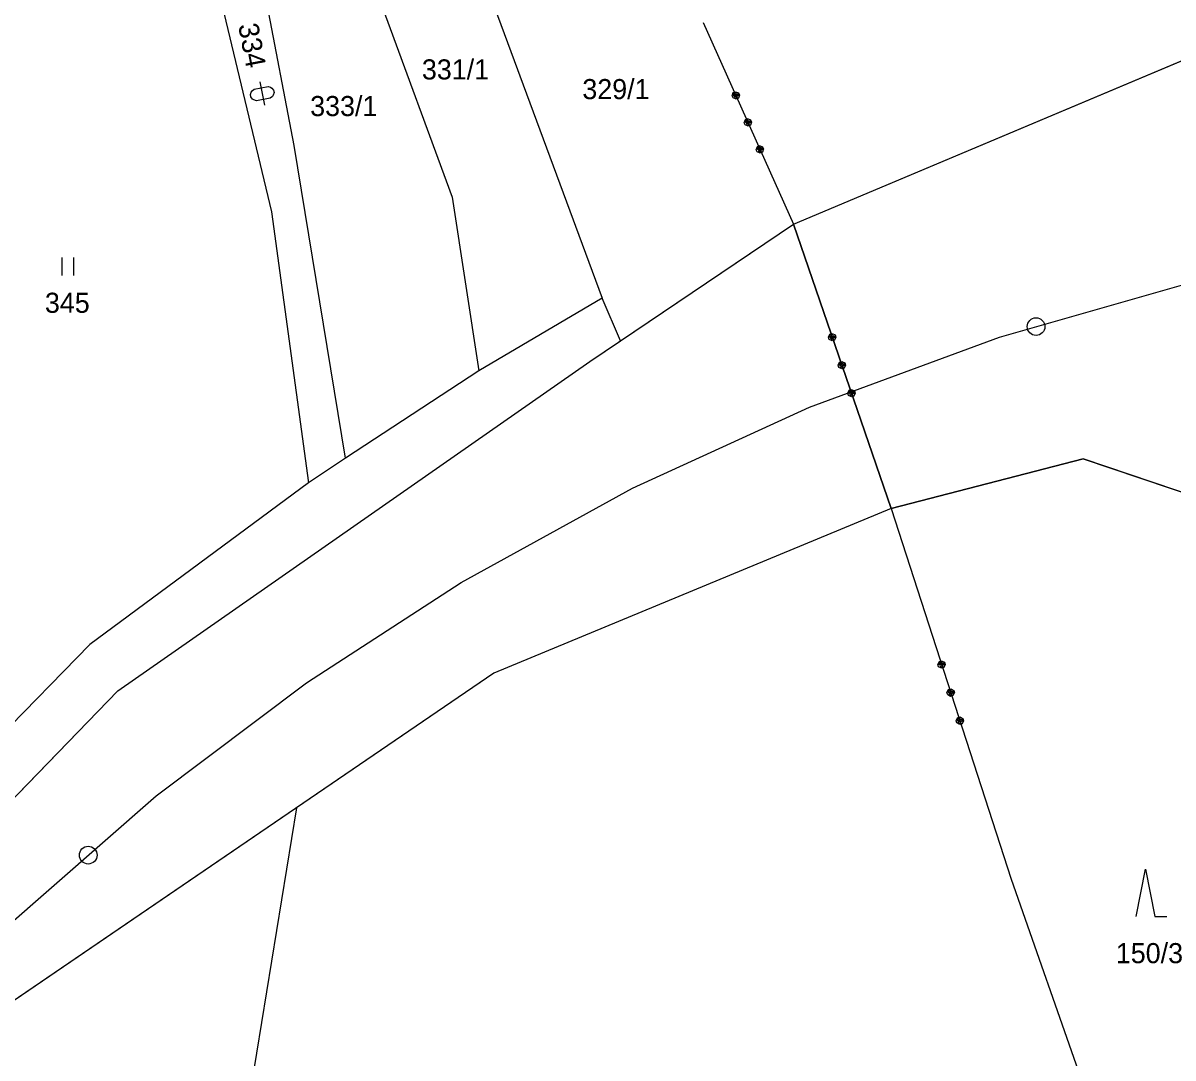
# Model space of a CAD drawing. Extents: x -866656 to -858817, y -1041816 to -1038653.
# Drawn here: x -863689.5 to -863592.2, y -1039792.1 to -1039704.6 of the extents above; entities that cross this region are included whole.
import ezdxf

# ---------------------------------------------------------------- set-up
doc = ezdxf.new("R2010")
doc.units = 0
for name, color, linetype in [('SZDC', 7, 'Continuous'), ('Vrstva 1', 7, 'Continuous'), ('Vrstva 3', 7, 'Continuous'), ('Vrstva 53', 7, 'Continuous'), ('Vrstva 7', 7, 'Continuous')]:
    doc.layers.add(name, color=color, linetype=linetype)

msp = doc.modelspace()

# ---------------------------------------------------------------- linework, layer by layer
at = {"layer": 'SZDC'}
for points in [[(-863578.248, -1039748.71), (-863599.78, -1039741.44), (-863616.033, -1039745.621), (-863624.298, -1039721.586), (-863586.128, -1039705.518)], [(-863782.379, -1039903.176), (-863748.01, -1039848.49), (-863725.76, -1039812), (-863710.18, -1039790.69), (-863681.49, -1039761.05), (-863641.52, -1039733.19), (-863638.923, -1039731.44), (-863624.298, -1039721.586), (-863616.033, -1039745.621), (-863649.65, -1039759.58), (-863666.36, -1039770.968), (-863692.07, -1039788.49), (-863713.604, -1039813.597), (-863754.65, -1039882.17)]]:
    msp.add_lwpolyline(points, dxfattribs=at)
at = {"layer": 'Vrstva 1'}
for p, q in [((-863666.548, -1039714.91), (-863673.173, -1039680.298)), ((-863677.665, -1039682.095), (-863668.457, -1039720.524)), ((-863653.972, -1039691.414), (-863640.48, -1039727.826)), ((-863659.137, -1039703.092), (-863653.186, -1039719.289)), ((-863624.298, -1039721.586), (-863586.128, -1039705.518)), ((-863670.117, -1039710.28), (-863669.939, -1039710.145)), ((-863669.939, -1039710.145), (-863668.76, -1039709.919)), ((-863669.444, -1039709.541), (-863669.068, -1039711.505)), ((-863668.76, -1039709.919), (-863668.545, -1039709.98)), ((-863668.545, -1039709.98), (-863668.428, -1039710.059)), ((-863668.428, -1039710.059), (-863668.292, -1039710.237)), ((-863670.257, -1039710.613), (-863670.196, -1039710.397)), ((-863670.219, -1039710.809), (-863670.257, -1039710.613)), ((-863670.083, -1039710.987), (-863670.219, -1039710.809)), ((-863670.196, -1039710.397), (-863670.117, -1039710.28)), ((-863669.966, -1039711.066), (-863670.083, -1039710.987)), ((-863669.751, -1039711.127), (-863669.966, -1039711.066)), ((-863668.572, -1039710.901), (-863669.751, -1039711.127)), ((-863668.395, -1039710.765), (-863668.572, -1039710.901)), ((-863668.315, -1039710.648), (-863668.395, -1039710.765)), ((-863668.255, -1039710.433), (-863668.315, -1039710.648)), ((-863668.292, -1039710.237), (-863668.255, -1039710.433)), ((-863662.208, -1039741.384), (-863666.548, -1039714.91)), ((-863653.186, -1039719.289), (-863650.91, -1039733.997)), ((-863668.457, -1039720.524), (-863665.337, -1039743.47)), ((-863641.52, -1039733.19), (-863624.298, -1039721.586)), ((-863686.229, -1039724.407), (-863686.229, -1039725.907)), ((-863685.229, -1039724.407), (-863685.229, -1039725.907)), ((-863640.48, -1039727.826), (-863650.91, -1039733.997)), ((-863638.923, -1039731.44), (-863640.48, -1039727.826)), ((-863681.49, -1039761.05), (-863641.52, -1039733.19)), ((-863650.91, -1039733.997), (-863662.208, -1039741.384)), ((-863662.208, -1039741.384), (-863665.337, -1039743.47)), ((-863616.033, -1039745.621), (-863599.78, -1039741.44)), ((-863599.78, -1039741.44), (-863573.262, -1039750.394)), ((-863665.337, -1039743.47), (-863683.849, -1039757.137)), ((-863616.033, -1039745.621), (-863649.65, -1039759.58)), ((-863683.849, -1039757.137), (-863714.528, -1039788.533)), ((-863649.65, -1039759.58), (-863692.07, -1039788.49)), ((-863710.18, -1039790.69), (-863681.49, -1039761.05)), ((-863666.36, -1039770.968), (-863672.36, -1039807.853)), ((-863595.29, -1039780.15), (-863594.49, -1039776.15)), ((-863594.49, -1039776.15), (-863593.69, -1039780.15)), ((-863593.69, -1039780.15), (-863592.69, -1039780.15))]:
    msp.add_line(p, q, dxfattribs=at)
msp.add_lwpolyline([(-863714.673, -1039807.18), (-863703.723, -1039794.072), (-863691.42, -1039781.486), (-863678.245, -1039769.939), (-863665.513, -1039760.373), (-863652.414, -1039751.898), (-863637.916, -1039743.904), (-863622.923, -1039737.063), (-863606.856, -1039731.127), (-863590.069, -1039726.347)], dxfattribs=at)
at = {"layer": 'Vrstva 3'}
for p, q in [((-863631.92, -1039704.52), (-863624.298, -1039721.586)), ((-863631.92, -1039704.52), (-863624.298, -1039721.586)), ((-863629.484, -1039710.71), (-863629.383, -1039710.446)), ((-863629.484, -1039710.71), (-863629.383, -1039710.446)), ((-863629.402, -1039710.892), (-863629.484, -1039710.71)), ((-863629.402, -1039710.892), (-863629.484, -1039710.71)), ((-863629.138, -1039710.993), (-863629.402, -1039710.892)), ((-863629.138, -1039710.993), (-863629.402, -1039710.892)), ((-863629.393, -1039710.669), (-863629.027, -1039710.506)), ((-863629.393, -1039710.669), (-863629.027, -1039710.506)), ((-863629.342, -1039710.537), (-863629.393, -1039710.669)), ((-863629.342, -1039710.537), (-863629.393, -1039710.669)), ((-863629.383, -1039710.446), (-863629.2, -1039710.364)), ((-863629.383, -1039710.446), (-863629.2, -1039710.364)), ((-863628.987, -1039710.597), (-863629.352, -1039710.76)), ((-863628.987, -1039710.597), (-863629.352, -1039710.76)), ((-863629.159, -1039710.455), (-863629.342, -1039710.537)), ((-863629.159, -1039710.455), (-863629.342, -1039710.537)), ((-863628.946, -1039710.688), (-863629.311, -1039710.852)), ((-863628.946, -1039710.688), (-863629.311, -1039710.852)), ((-863629.311, -1039710.852), (-863629.179, -1039710.902)), ((-863629.311, -1039710.852), (-863629.179, -1039710.902)), ((-863629.2, -1039710.364), (-863628.936, -1039710.465)), ((-863629.2, -1039710.364), (-863628.936, -1039710.465)), ((-863629.179, -1039710.902), (-863628.996, -1039710.821)), ((-863629.179, -1039710.902), (-863628.996, -1039710.821)), ((-863628.955, -1039710.912), (-863629.138, -1039710.993)), ((-863628.955, -1039710.912), (-863629.138, -1039710.993)), ((-863629.027, -1039710.506), (-863628.946, -1039710.688)), ((-863629.027, -1039710.506), (-863628.946, -1039710.688)), ((-863628.854, -1039710.648), (-863628.955, -1039710.912)), ((-863628.854, -1039710.648), (-863628.955, -1039710.912)), ((-863628.936, -1039710.465), (-863628.854, -1039710.648)), ((-863628.936, -1039710.465), (-863628.854, -1039710.648)), ((-863628.464, -1039712.992), (-863628.363, -1039712.728)), ((-863628.464, -1039712.992), (-863628.363, -1039712.728)), ((-863628.383, -1039713.175), (-863628.464, -1039712.992)), ((-863628.383, -1039713.175), (-863628.464, -1039712.992)), ((-863628.373, -1039712.952), (-863628.008, -1039712.789)), ((-863628.373, -1039712.952), (-863628.008, -1039712.789)), ((-863628.323, -1039712.82), (-863628.373, -1039712.952)), ((-863628.323, -1039712.82), (-863628.373, -1039712.952)), ((-863628.363, -1039712.728), (-863628.181, -1039712.647)), ((-863628.363, -1039712.728), (-863628.181, -1039712.647)), ((-863627.967, -1039712.88), (-863628.332, -1039713.043)), ((-863627.967, -1039712.88), (-863628.332, -1039713.043)), ((-863628.14, -1039712.738), (-863628.323, -1039712.82)), ((-863628.14, -1039712.738), (-863628.323, -1039712.82)), ((-863627.926, -1039712.971), (-863628.292, -1039713.134)), ((-863627.926, -1039712.971), (-863628.292, -1039713.134)), ((-863628.181, -1039712.647), (-863627.917, -1039712.748)), ((-863628.181, -1039712.647), (-863627.917, -1039712.748)), ((-863628.008, -1039712.789), (-863627.926, -1039712.971)), ((-863628.008, -1039712.789), (-863627.926, -1039712.971)), ((-863627.835, -1039712.93), (-863627.936, -1039713.195)), ((-863627.835, -1039712.93), (-863627.936, -1039713.195)), ((-863627.917, -1039712.748), (-863627.835, -1039712.93)), ((-863627.917, -1039712.748), (-863627.835, -1039712.93)), ((-863628.119, -1039713.276), (-863628.383, -1039713.175)), ((-863628.119, -1039713.276), (-863628.383, -1039713.175)), ((-863628.292, -1039713.134), (-863628.16, -1039713.185)), ((-863628.292, -1039713.134), (-863628.16, -1039713.185)), ((-863628.16, -1039713.185), (-863627.977, -1039713.103)), ((-863628.16, -1039713.185), (-863627.977, -1039713.103)), ((-863627.936, -1039713.195), (-863628.119, -1039713.276)), ((-863627.936, -1039713.195), (-863628.119, -1039713.276)), ((-863627.445, -1039715.275), (-863627.344, -1039715.011)), ((-863627.445, -1039715.275), (-863627.344, -1039715.011)), ((-863627.344, -1039715.011), (-863627.161, -1039714.929)), ((-863627.344, -1039715.011), (-863627.161, -1039714.929)), ((-863627.121, -1039715.021), (-863627.303, -1039715.102)), ((-863627.121, -1039715.021), (-863627.303, -1039715.102)), ((-863627.161, -1039714.929), (-863626.897, -1039715.031)), ((-863627.161, -1039714.929), (-863626.897, -1039715.031)), ((-863627.364, -1039715.458), (-863627.445, -1039715.275)), ((-863627.364, -1039715.458), (-863627.445, -1039715.275)), ((-863627.099, -1039715.559), (-863627.364, -1039715.458)), ((-863627.099, -1039715.559), (-863627.364, -1039715.458)), ((-863627.354, -1039715.234), (-863626.989, -1039715.071)), ((-863627.354, -1039715.234), (-863626.989, -1039715.071)), ((-863627.303, -1039715.102), (-863627.354, -1039715.234)), ((-863627.303, -1039715.102), (-863627.354, -1039715.234)), ((-863626.948, -1039715.163), (-863627.313, -1039715.326)), ((-863626.948, -1039715.163), (-863627.313, -1039715.326)), ((-863626.907, -1039715.254), (-863627.272, -1039715.417)), ((-863626.907, -1039715.254), (-863627.272, -1039715.417)), ((-863627.272, -1039715.417), (-863627.14, -1039715.468)), ((-863627.272, -1039715.417), (-863627.14, -1039715.468)), ((-863627.14, -1039715.468), (-863626.958, -1039715.386)), ((-863627.14, -1039715.468), (-863626.958, -1039715.386)), ((-863626.917, -1039715.477), (-863627.099, -1039715.559)), ((-863626.917, -1039715.477), (-863627.099, -1039715.559)), ((-863626.989, -1039715.071), (-863626.907, -1039715.254)), ((-863626.989, -1039715.071), (-863626.907, -1039715.254)), ((-863626.816, -1039715.213), (-863626.917, -1039715.477)), ((-863626.816, -1039715.213), (-863626.917, -1039715.477)), ((-863626.897, -1039715.031), (-863626.816, -1039715.213)), ((-863626.897, -1039715.031), (-863626.816, -1039715.213)), ((-863624.298, -1039721.586), (-863616.033, -1039745.621)), ((-863624.298, -1039721.586), (-863616.033, -1039745.621)), ((-863621.327, -1039731.148), (-863621.203, -1039730.894)), ((-863621.327, -1039731.148), (-863621.203, -1039730.894)), ((-863621.262, -1039731.337), (-863621.327, -1039731.148)), ((-863621.262, -1039731.337), (-863621.327, -1039731.148)), ((-863621.008, -1039731.461), (-863621.262, -1039731.337)), ((-863621.008, -1039731.461), (-863621.262, -1039731.337)), ((-863621.233, -1039731.115), (-863620.855, -1039730.985)), ((-863621.233, -1039731.115), (-863620.855, -1039730.985)), ((-863621.171, -1039730.988), (-863621.233, -1039731.115)), ((-863621.171, -1039730.988), (-863621.233, -1039731.115)), ((-863621.203, -1039730.894), (-863621.014, -1039730.829)), ((-863621.203, -1039730.894), (-863621.014, -1039730.829)), ((-863620.822, -1039731.08), (-863621.2, -1039731.21)), ((-863620.822, -1039731.08), (-863621.2, -1039731.21)), ((-863620.982, -1039730.923), (-863621.171, -1039730.988)), ((-863620.982, -1039730.923), (-863621.171, -1039730.988)), ((-863620.79, -1039731.174), (-863621.168, -1039731.304)), ((-863620.79, -1039731.174), (-863621.168, -1039731.304)), ((-863621.168, -1039731.304), (-863621.041, -1039731.367)), ((-863621.168, -1039731.304), (-863621.041, -1039731.367)), ((-863621.041, -1039731.367), (-863620.852, -1039731.301)), ((-863621.041, -1039731.367), (-863620.852, -1039731.301)), ((-863621.014, -1039730.829), (-863620.76, -1039730.953)), ((-863621.014, -1039730.829), (-863620.76, -1039730.953)), ((-863620.819, -1039731.396), (-863621.008, -1039731.461)), ((-863620.819, -1039731.396), (-863621.008, -1039731.461)), ((-863620.855, -1039730.985), (-863620.79, -1039731.174)), ((-863620.855, -1039730.985), (-863620.79, -1039731.174)), ((-863620.695, -1039731.142), (-863620.819, -1039731.396)), ((-863620.695, -1039731.142), (-863620.819, -1039731.396)), ((-863620.76, -1039730.953), (-863620.695, -1039731.142)), ((-863620.76, -1039730.953), (-863620.695, -1039731.142)), ((-863620.514, -1039733.512), (-863620.39, -1039733.258)), ((-863620.514, -1039733.512), (-863620.39, -1039733.258)), ((-863620.449, -1039733.701), (-863620.514, -1039733.512)), ((-863620.449, -1039733.701), (-863620.514, -1039733.512)), ((-863620.42, -1039733.479), (-863620.042, -1039733.349)), ((-863620.42, -1039733.479), (-863620.042, -1039733.349)), ((-863620.358, -1039733.352), (-863620.42, -1039733.479)), ((-863620.358, -1039733.352), (-863620.42, -1039733.479)), ((-863620.39, -1039733.258), (-863620.201, -1039733.193)), ((-863620.39, -1039733.258), (-863620.201, -1039733.193)), ((-863620.009, -1039733.444), (-863620.387, -1039733.574)), ((-863620.009, -1039733.444), (-863620.387, -1039733.574)), ((-863620.169, -1039733.287), (-863620.358, -1039733.352)), ((-863620.169, -1039733.287), (-863620.358, -1039733.352)), ((-863620.201, -1039733.193), (-863619.947, -1039733.317)), ((-863620.201, -1039733.193), (-863619.947, -1039733.317)), ((-863620.042, -1039733.349), (-863619.977, -1039733.538)), ((-863620.042, -1039733.349), (-863619.977, -1039733.538)), ((-863619.882, -1039733.506), (-863620.006, -1039733.76)), ((-863619.882, -1039733.506), (-863620.006, -1039733.76)), ((-863619.947, -1039733.317), (-863619.882, -1039733.506)), ((-863619.947, -1039733.317), (-863619.882, -1039733.506)), ((-863620.195, -1039733.825), (-863620.449, -1039733.701)), ((-863620.195, -1039733.825), (-863620.449, -1039733.701)), ((-863619.977, -1039733.538), (-863620.355, -1039733.669)), ((-863619.977, -1039733.538), (-863620.355, -1039733.669)), ((-863620.355, -1039733.669), (-863620.228, -1039733.731)), ((-863620.355, -1039733.669), (-863620.228, -1039733.731)), ((-863620.228, -1039733.731), (-863620.039, -1039733.666)), ((-863620.228, -1039733.731), (-863620.039, -1039733.666)), ((-863620.006, -1039733.76), (-863620.195, -1039733.825)), ((-863620.006, -1039733.76), (-863620.195, -1039733.825)), ((-863619.701, -1039735.876), (-863619.577, -1039735.622)), ((-863619.701, -1039735.876), (-863619.577, -1039735.622)), ((-863619.636, -1039736.065), (-863619.701, -1039735.876)), ((-863619.636, -1039736.065), (-863619.701, -1039735.876)), ((-863619.382, -1039736.189), (-863619.636, -1039736.065)), ((-863619.382, -1039736.189), (-863619.636, -1039736.065)), ((-863619.607, -1039735.844), (-863619.229, -1039735.713)), ((-863619.607, -1039735.844), (-863619.229, -1039735.713)), ((-863619.545, -1039735.716), (-863619.607, -1039735.844)), ((-863619.545, -1039735.716), (-863619.607, -1039735.844)), ((-863619.577, -1039735.622), (-863619.388, -1039735.557)), ((-863619.577, -1039735.622), (-863619.388, -1039735.557)), ((-863619.196, -1039735.808), (-863619.574, -1039735.938)), ((-863619.196, -1039735.808), (-863619.574, -1039735.938)), ((-863619.356, -1039735.651), (-863619.545, -1039735.716)), ((-863619.356, -1039735.651), (-863619.545, -1039735.716)), ((-863619.164, -1039735.903), (-863619.542, -1039736.033)), ((-863619.164, -1039735.903), (-863619.542, -1039736.033)), ((-863619.542, -1039736.033), (-863619.415, -1039736.095)), ((-863619.542, -1039736.033), (-863619.415, -1039736.095)), ((-863619.415, -1039736.095), (-863619.226, -1039736.03)), ((-863619.415, -1039736.095), (-863619.226, -1039736.03)), ((-863619.388, -1039735.557), (-863619.134, -1039735.681)), ((-863619.388, -1039735.557), (-863619.134, -1039735.681)), ((-863619.193, -1039736.124), (-863619.382, -1039736.189)), ((-863619.193, -1039736.124), (-863619.382, -1039736.189)), ((-863619.229, -1039735.713), (-863619.164, -1039735.903)), ((-863619.229, -1039735.713), (-863619.164, -1039735.903)), ((-863619.069, -1039735.87), (-863619.193, -1039736.124)), ((-863619.069, -1039735.87), (-863619.193, -1039736.124)), ((-863619.134, -1039735.681), (-863619.069, -1039735.87)), ((-863619.134, -1039735.681), (-863619.069, -1039735.87)), ((-863616.033, -1039745.621), (-863605.87, -1039777)), ((-863616.033, -1039745.621), (-863605.87, -1039777)), ((-863612.069, -1039758.834), (-863611.94, -1039758.582)), ((-863612.069, -1039758.834), (-863611.94, -1039758.582)), ((-863611.909, -1039758.677), (-863611.973, -1039758.803)), ((-863611.909, -1039758.677), (-863611.973, -1039758.803)), ((-863611.973, -1039758.803), (-863611.593, -1039758.68)), ((-863611.973, -1039758.803), (-863611.593, -1039758.68)), ((-863611.562, -1039758.775), (-863611.943, -1039758.898)), ((-863611.562, -1039758.775), (-863611.943, -1039758.898)), ((-863611.94, -1039758.582), (-863611.75, -1039758.521)), ((-863611.94, -1039758.582), (-863611.75, -1039758.521)), ((-863611.719, -1039758.616), (-863611.909, -1039758.677)), ((-863611.719, -1039758.616), (-863611.909, -1039758.677)), ((-863611.75, -1039758.521), (-863611.498, -1039758.649)), ((-863611.75, -1039758.521), (-863611.498, -1039758.649)), ((-863611.593, -1039758.68), (-863611.531, -1039758.87)), ((-863611.593, -1039758.68), (-863611.531, -1039758.87)), ((-863611.498, -1039758.649), (-863611.436, -1039758.84)), ((-863611.498, -1039758.649), (-863611.436, -1039758.84)), ((-863612.007, -1039759.024), (-863612.069, -1039758.834)), ((-863612.007, -1039759.024), (-863612.069, -1039758.834)), ((-863611.755, -1039759.153), (-863612.007, -1039759.024)), ((-863611.755, -1039759.153), (-863612.007, -1039759.024)), ((-863611.531, -1039758.87), (-863611.912, -1039758.994)), ((-863611.531, -1039758.87), (-863611.912, -1039758.994)), ((-863611.912, -1039758.994), (-863611.786, -1039759.058)), ((-863611.912, -1039758.994), (-863611.786, -1039759.058)), ((-863611.786, -1039759.058), (-863611.596, -1039758.996)), ((-863611.786, -1039759.058), (-863611.596, -1039758.996)), ((-863611.565, -1039759.091), (-863611.755, -1039759.153)), ((-863611.565, -1039759.091), (-863611.755, -1039759.153)), ((-863611.436, -1039758.84), (-863611.565, -1039759.091)), ((-863611.436, -1039758.84), (-863611.565, -1039759.091)), ((-863611.298, -1039761.212), (-863611.17, -1039760.961)), ((-863611.298, -1039761.212), (-863611.17, -1039760.961)), ((-863611.237, -1039761.403), (-863611.298, -1039761.212)), ((-863611.237, -1039761.403), (-863611.298, -1039761.212)), ((-863610.985, -1039761.531), (-863611.237, -1039761.403)), ((-863610.985, -1039761.531), (-863611.237, -1039761.403)), ((-863611.139, -1039761.056), (-863611.203, -1039761.182)), ((-863611.139, -1039761.056), (-863611.203, -1039761.182)), ((-863611.203, -1039761.182), (-863610.823, -1039761.058)), ((-863611.203, -1039761.182), (-863610.823, -1039761.058)), ((-863610.792, -1039761.154), (-863611.172, -1039761.277)), ((-863610.792, -1039761.154), (-863611.172, -1039761.277)), ((-863611.17, -1039760.961), (-863610.979, -1039760.899)), ((-863611.17, -1039760.961), (-863610.979, -1039760.899)), ((-863610.761, -1039761.249), (-863611.141, -1039761.372)), ((-863610.761, -1039761.249), (-863611.141, -1039761.372)), ((-863611.141, -1039761.372), (-863611.016, -1039761.436)), ((-863611.141, -1039761.372), (-863611.016, -1039761.436)), ((-863610.949, -1039760.994), (-863611.139, -1039761.056)), ((-863610.949, -1039760.994), (-863611.139, -1039761.056)), ((-863611.016, -1039761.436), (-863610.825, -1039761.375)), ((-863611.016, -1039761.436), (-863610.825, -1039761.375)), ((-863610.794, -1039761.47), (-863610.985, -1039761.531)), ((-863610.794, -1039761.47), (-863610.985, -1039761.531)), ((-863610.979, -1039760.899), (-863610.727, -1039761.028)), ((-863610.979, -1039760.899), (-863610.727, -1039761.028)), ((-863610.823, -1039761.058), (-863610.761, -1039761.249)), ((-863610.823, -1039761.058), (-863610.761, -1039761.249)), ((-863610.666, -1039761.218), (-863610.794, -1039761.47)), ((-863610.666, -1039761.218), (-863610.794, -1039761.47)), ((-863610.727, -1039761.028), (-863610.666, -1039761.218)), ((-863610.727, -1039761.028), (-863610.666, -1039761.218)), ((-863610.528, -1039763.591), (-863610.399, -1039763.339)), ((-863610.528, -1039763.591), (-863610.399, -1039763.339)), ((-863610.466, -1039763.781), (-863610.528, -1039763.591)), ((-863610.466, -1039763.781), (-863610.528, -1039763.591)), ((-863610.368, -1039763.434), (-863610.433, -1039763.56)), ((-863610.368, -1039763.434), (-863610.433, -1039763.56)), ((-863610.433, -1039763.56), (-863610.052, -1039763.437)), ((-863610.433, -1039763.56), (-863610.052, -1039763.437)), ((-863610.021, -1039763.532), (-863610.402, -1039763.655)), ((-863610.021, -1039763.532), (-863610.402, -1039763.655)), ((-863610.399, -1039763.339), (-863610.209, -1039763.277)), ((-863610.399, -1039763.339), (-863610.209, -1039763.277)), ((-863609.991, -1039763.627), (-863610.371, -1039763.75)), ((-863609.991, -1039763.627), (-863610.371, -1039763.75)), ((-863610.178, -1039763.372), (-863610.368, -1039763.434)), ((-863610.178, -1039763.372), (-863610.368, -1039763.434)), ((-863610.209, -1039763.277), (-863609.957, -1039763.406)), ((-863610.209, -1039763.277), (-863609.957, -1039763.406)), ((-863610.052, -1039763.437), (-863609.991, -1039763.627)), ((-863610.052, -1039763.437), (-863609.991, -1039763.627)), ((-863609.895, -1039763.596), (-863610.024, -1039763.848)), ((-863609.895, -1039763.596), (-863610.024, -1039763.848)), ((-863609.957, -1039763.406), (-863609.895, -1039763.596)), ((-863609.957, -1039763.406), (-863609.895, -1039763.596)), ((-863610.214, -1039763.91), (-863610.466, -1039763.781)), ((-863610.214, -1039763.91), (-863610.466, -1039763.781)), ((-863610.371, -1039763.75), (-863610.245, -1039763.815)), ((-863610.371, -1039763.75), (-863610.245, -1039763.815)), ((-863610.245, -1039763.815), (-863610.055, -1039763.753)), ((-863610.245, -1039763.815), (-863610.055, -1039763.753)), ((-863610.024, -1039763.848), (-863610.214, -1039763.91)), ((-863610.024, -1039763.848), (-863610.214, -1039763.91)), ((-863605.87, -1039777), (-863590.51, -1039820.72)), ((-863605.87, -1039777), (-863590.51, -1039820.72))]:
    msp.add_line(p, q, dxfattribs=at)
at = {"layer": 'Vrstva 53'}
for points in [[(-863782.379, -1039903.177), (-863748.01, -1039848.491), (-863725.76, -1039812.001), (-863710.18, -1039790.691), (-863681.49, -1039761.051), (-863641.52, -1039733.191), (-863638.923, -1039731.441), (-863624.298, -1039721.586), (-863586.128, -1039705.518)], [(-863578.248, -1039748.71), (-863599.78, -1039741.44), (-863616.033, -1039745.621), (-863649.65, -1039759.581), (-863666.36, -1039770.969), (-863692.07, -1039788.491), (-863713.604, -1039813.598), (-863754.65, -1039882.171)]]:
    msp.add_lwpolyline(points, dxfattribs=at)
at = {"layer": 'Vrstva 7'}
for centre in [(-863603.759, -1039730.245), (-863683.984, -1039774.969)]:
    msp.add_circle(centre, 0.75, dxfattribs=at)

# ---------------------------------------------------------------- texts
at = {"layer": 'Vrstva 1'}
msp.add_text('334', height=1.7, rotation=280.83554, dxfattribs=at).set_placement((-863671.299, -1039704.733))
for s, p in [('331/1', (-863655.74, -1039709.331)), ('329/1', (-863642.16, -1039710.996)), ('333/1', (-863665.197, -1039712.43)), ('345', (-863687.648, -1039729.076)), ('150/3', (-863597.004, -1039784.11))]:
    msp.add_text(s, height=1.7, dxfattribs=at).set_placement(p)

doc.saveas('drawing.dxf')
